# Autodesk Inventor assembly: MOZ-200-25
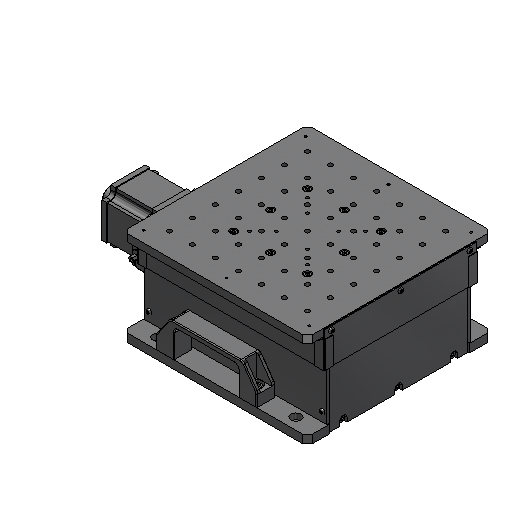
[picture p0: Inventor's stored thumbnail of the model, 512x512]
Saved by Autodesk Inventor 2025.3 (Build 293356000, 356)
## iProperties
RuleStatus: InUse
Created: 2019-09
Vendor: OPTICS FOCUS
Document SubType Name: Assembly
Designer: arnoldj
Part Number: MOZ-200-25
Description: MOTORIZED VERTICAL LIFT STAGE
AfterDocSave0: file://Part Number Cleaner
DESIGN DEPARTMENT: HHMI: JRC - ID&F
ALTERED ITEM PART NUMBER: N/A
ALTERED ITEM VENDOR: N/A
ALTERED ITEM DESCRIPTION: N/A
Author: arnoldj
Revision Number: 0
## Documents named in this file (3)
- C:\_WORKSPACE\DATA\COMMON\Optics Focus\OPTICS FOCUS MOZ-200-25.iam
- C:\_WORKSPACE\DATA\COMMON\Optics Focus\OPTICS FOCUS MOZ-200-25_BASE.ipt
- C:\_WORKSPACE\DATA\COMMON\Optics Focus\OPTICS FOCUS_MOZ-200-25_CARR.ipt
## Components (2 placed, 2 different names)
1. OPTICS FOCUS MOZ-200-25_BASE:1 — Flush:1, Flush:2, Mate:1
2. OPTICS FOCUS_MOZ-200-25_CARR:1 — Flush:1, Flush:2, Mate:1
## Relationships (3: Flush 2, Mate 1)
- Flush:1: OPTICS FOCUS MOZ-200-25_BASE:1 ↔ OPTICS FOCUS_MOZ-200-25_CARR:1
- Flush:2: OPTICS FOCUS MOZ-200-25_BASE:1 ↔ OPTICS FOCUS_MOZ-200-25_CARR:1
- Mate:1: OPTICS FOCUS MOZ-200-25_BASE:1 ↔ OPTICS FOCUS_MOZ-200-25_CARR:1
